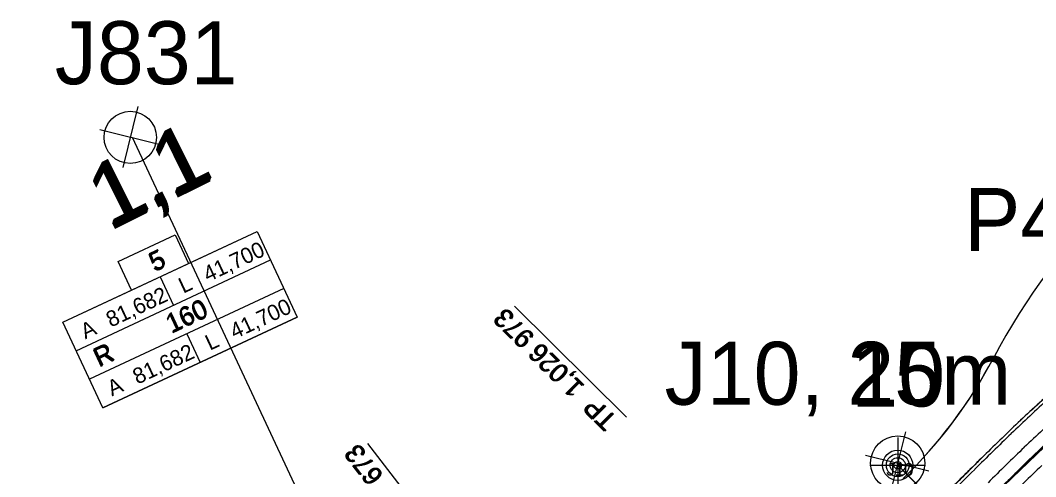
# Model space of a CAD drawing. Extents: x -606444 to -604546, y -1158114 to -1156869.
# Drawn here: x -605873.5 to -605712.4, y -1157200.2 to -1157127.7 of the extents above; entities that cross this region are included whole.
import ezdxf

# ---------------------------------------------------------------- set-up
doc = ezdxf.new("R2010")
doc.units = 0
for name, color, linetype in [('0_sondy', 7, 'Continuous'), ('ARCHIVNÍ SONDY', 7, 'Continuous'), ('B_TRAM', 7, 'Continuous'), ('B_ZELEN', 7, 'Continuous'), ('geofyzikální profily_předběžný GTP', 7, 'Continuous'), ('jádrové vrty_předběžný GTP', 7, 'Continuous'), ('netisk', 7, 'Continuous'), ('netisk2', 7, 'Continuous'), ('NS_VB', 7, 'Continuous'), ('NS_VB_OBJ', 7, 'Continuous'), ('OSA', 7, 'Continuous'), ('OSAPOP', 7, 'Continuous'), ('podélný profil trasou tramvaje', 7, 'Continuous'), ('sondy předběžného průzkumu', 7, 'Continuous'), ('sondy současného průzkumu', 7, 'Continuous')]:
    doc.layers.add(name, color=color, linetype=linetype)

# ---------------------------------------------------------------- blocks, each defined once
blk = doc.blocks.new('709')
for p, q in [((0, 2.2), (0, -2.2)), ((-2.2, 0), (2.2, 0))]:
    blk.add_line(p, q)
for radius in [1.2, 0.9, 0.6, 0.3]:
    blk.add_circle((0, 0), radius)
blk = doc.blocks.new('IG vrt podr')
at = {"layer": 'sondy současného průzkumu'}
for p, q in [((0.412, 1.649), (-0.418, -1.672)), ((-1.698, 0.422), (1.644, -0.408))]:
    blk.add_line(p, q, dxfattribs=at)
blk.add_circle((-0.002, 0.001), 1.434, dxfattribs=at)
blk = doc.blocks.new('IG vrt archivní')
at = {"layer": 'sondy předběžného průzkumu'}
for p, q in [((0.406, 1.636), (-0.393, -1.584)), ((1.589, -0.397), (-1.612, 0.402))]:
    blk.add_line(p, q, dxfattribs=at)
blk.add_circle((0.001, 0.002), 1.382, dxfattribs=at)

msp = doc.modelspace()

# ---------------------------------------------------------------- linework, layer by layer
for q in [(-605734.42, -1157197.95), (-605734.42, -1157198.15), (-605734.22, -1157197.95), (-605734.22, -1157198.15)]:
    msp.add_line((-605734.32, -1157198.05), q)
at = {"layer": 'B_TRAM'}
for centre, radius, start, end in [((-605516.94, -1157401), 288.36, 132.2227, 133.8432), ((-605396.37, -1157526.55), 462.42, 133.8432, 134.8464), ((-604880.81, -1158044.88), 1193.49, 134.84638, 135.23211)]:
    msp.add_arc(centre, radius, start, end, dxfattribs=at)
at = {"layer": 'B_ZELEN'}
for centre, radius, start, end in [((-605630.61, -1157227.84), 100, 115.0835, 152.312), ((-605786.09, -1157146.2), 75.62, 314.1042, 332.277), ((-605503.99, -1157414.87), 307.33, 132.2728, 133.7932), ((-605425.68, -1157496.55), 420.48, 133.7932, 134.8964), ((-604572.51, -1158352.82), 1629.25, 134.89641, 135.21406)]:
    msp.add_arc(centre, radius, start, end, dxfattribs=at)
at = {"layer": 'geofyzikální profily_předběžný GTP'}
msp.add_spline([(-605950.45, -1157295.92), (-605904.87, -1157291.72), (-605856.97, -1157287.39), (-605826.74, -1157281.64), (-605800.72, -1157271.74), (-605782.37, -1157261.31), (-605766.27, -1157249.35), (-605744.49, -1157228.62), (-605716.54, -1157200.55), (-605701.17, -1157186.19), (-605682.49, -1157172.86), (-605668.89, -1157164.85), (-605653.7, -1157158.02), (-605640.64, -1157153.35), (-605624.44, -1157148.58)], degree=3, dxfattribs=at)
at = {"layer": 'netisk'}
for p, q in [((-605799.38, -1157266.89), (-605855.73, -1157146.35)), ((-605725.18, -1157207.75), (-605734.33, -1157198.4))]:
    msp.add_line(p, q, dxfattribs=at)
at = {"layer": 'netisk2'}
msp.add_line((-605734.33, -1157198.4), (-605724.33, -1157208.33), dxfattribs=at)
at = {"layer": 'NS_VB'}
msp.add_line((-605732.76, -1157199.79), (-605733.47, -1157200.5), dxfattribs=at)
for centre, radius, start, end in [((-605630.61, -1157227.84), 100, 115.0835, 152.312), ((-605785.57, -1157146.53), 75, 315.2037, 332.312), ((-605516.94, -1157401), 288.36, 132.2227, 133.8432), ((-605396.37, -1157526.55), 462.42, 133.8432, 134.8464), ((-604880.81, -1158044.88), 1193.49, 134.84638, 135.23211), ((-604880.81, -1158044.88), 1199.99, 135.20366, 135.23198), ((-604880.81, -1158044.88), 1175.99, 134.05156, 135.23246)]:
    msp.add_arc(centre, radius, start, end, dxfattribs=at)
at = {"layer": 'NS_VB_OBJ'}
for centre, radius, start, end in [((-605516.94, -1157401), 287.86, 132.2227, 133.8432), ((-605396.37, -1157526.55), 461.92, 133.8432, 134.8464), ((-604880.81, -1158044.88), 1192.99, 134.84638, 135.13951)]:
    msp.add_arc(centre, radius, start, end, dxfattribs=at)
at = {"layer": 'OSA'}
for centre, radius, start, end in [((-605516.94, -1157401), 284.86, 132.2227, 133.8432), ((-605516.94, -1157401), 282.86, 132.2227, 133.8432), ((-605396.37, -1157526.55), 458.92, 133.8432, 134.8464), ((-605396.37, -1157526.55), 456.92, 133.8432, 134.8464), ((-605396.37, -1157526.55), 454.92, 133.8432, 134.8464)]:
    msp.add_arc(centre, radius, start, end, dxfattribs=at)
at = {"layer": 'OSAPOP'}
for p, q in [((-605846.83, -1157166.36), (-605835.96, -1157161.28)), ((-605864.64, -1157180.21), (-605833.84, -1157165.81)), ((-605855.89, -1157170.6), (-605846.83, -1157166.36)), ((-605851.36, -1157168.48), (-605849.24, -1157173.01)), ((-605866.76, -1157175.68), (-605855.89, -1157170.6)), ((-605831.72, -1157170.34), (-605862.52, -1157184.74)), ((-605777.37, -1157190.78), (-605795.11, -1157173.16)), ((-605860.41, -1157189.27), (-605829.61, -1157174.87)), ((-605847.12, -1157177.54), (-605845.01, -1157182.07)), ((-605803.12, -1157214.73), (-605818.41, -1157194.95))]:
    msp.add_line(p, q, dxfattribs=at)
msp.add_lwpolyline([(-605866.76, -1157175.68), (-605835.96, -1157161.28), (-605829.61, -1157174.87), (-605860.41, -1157189.27)], close=True, dxfattribs=at)
msp.add_lwpolyline([(-605855.89, -1157170.6), (-605858.01, -1157166.07), (-605848.95, -1157161.83), (-605846.83, -1157166.36)], dxfattribs=at)
at = {"layer": 'podélný profil trasou tramvaje'}
msp.add_lwpolyline([(-605747.06, -1157230.38), (-605721.43, -1157205.41), (-605705.79, -1157190.43), (-605700.85, -1157186.24), (-605685.05, -1157174.36), (-605668.25, -1157164.47)], dxfattribs=at)

# ---------------------------------------------------------------- block references
at = {"layer": '0_sondy', "xscale": 2, "yscale": 2}
msp.add_blockref('709', (-605734.33, -1157198.4), dxfattribs=at)
at = {"layer": 'ARCHIVNÍ SONDY', "xscale": 3, "yscale": 3}
msp.add_blockref('IG vrt archivní', (-605856.08, -1157146.35), dxfattribs=at)
at = {"layer": 'jádrové vrty_předběžný GTP', "xscale": 3, "yscale": 3}
msp.add_blockref('IG vrt podr', (-605734.32, -1157198.05), dxfattribs=at)

# ---------------------------------------------------------------- texts
msp.add_text('J10', height=2).set_placement((-605736.13, -1157200.05))
at = {"layer": '0_sondy'}
msp.add_text('10', height=10, dxfattribs=at).set_placement((-605741.69, -1157189.08))
at = {"layer": 'ARCHIVNÍ SONDY'}
msp.add_text('J831', height=10, dxfattribs=at).set_placement((-605868.05, -1157137.9))
at = {"layer": 'geofyzikální profily_předběžný GTP'}
msp.add_text('P4', height=10, dxfattribs=at).set_placement((-605723.8, -1157164.39))
at = {"layer": 'jádrové vrty_předběžný GTP'}
msp.add_text('J10, 25m', height=10, dxfattribs=at).set_placement((-605771.31, -1157188.8))
at = {"layer": 'OSAPOP'}
for s, height, rotation, p in [('1,1', 10, 26.5011, (-605859.42, -1157161.34)), ('1,1', 10, 26.5011, (-605859.35, -1157161.14)), ('1,1', 10, 26.5011, (-605859.29, -1157160.94)), ('1,1', 10, 26.5011, (-605859.22, -1157160.74)), ('41,700', 2.5, 25.0533, (-605843.77, -1157169.35)), ('5', 3, 25.0533, (-605852.24, -1157167.79)), ('5', 3, 25.0533, (-605852.16, -1157167.59)), ('L', 2.5, 25.0533, (-605847.67, -1157171.17)), ('81,682', 2.5, 25.0533, (-605859.17, -1157176.55)), ('160', 3, 25.0533, (-605849.57, -1157177.58)), ('160', 3, 25.0533, (-605849.5, -1157177.38)), ('41,700', 2.5, 25.0533, (-605839.53, -1157178.41)), ('TP  1,026 973', 3, 135.1856, (-605778.79, -1157191)), ('TP  1,026 973', 3, 135.1856, (-605778.57, -1157191)), ('A', 2.5, 25.0533, (-605863.22, -1157178.44)), ('L', 2.5, 25.0533, (-605843.44, -1157180.23)), ('R', 3, 25.0533, (-605861.05, -1157182.94)), ('R', 3, 25.0533, (-605860.97, -1157182.74)), ('81,682', 2.5, 25.0533, (-605854.94, -1157185.61)), ('A', 2.5, 25.0533, (-605858.99, -1157187.5)), ('PK  1,068 673', 3, 127.7192, (-605804.46, -1157214.88)), ('PK  1,068 673', 3, 127.7192, (-605804.25, -1157214.9))]:
    msp.add_text(s, height=height, rotation=rotation, dxfattribs=at).set_placement(p)

doc.saveas('drawing.dxf')
